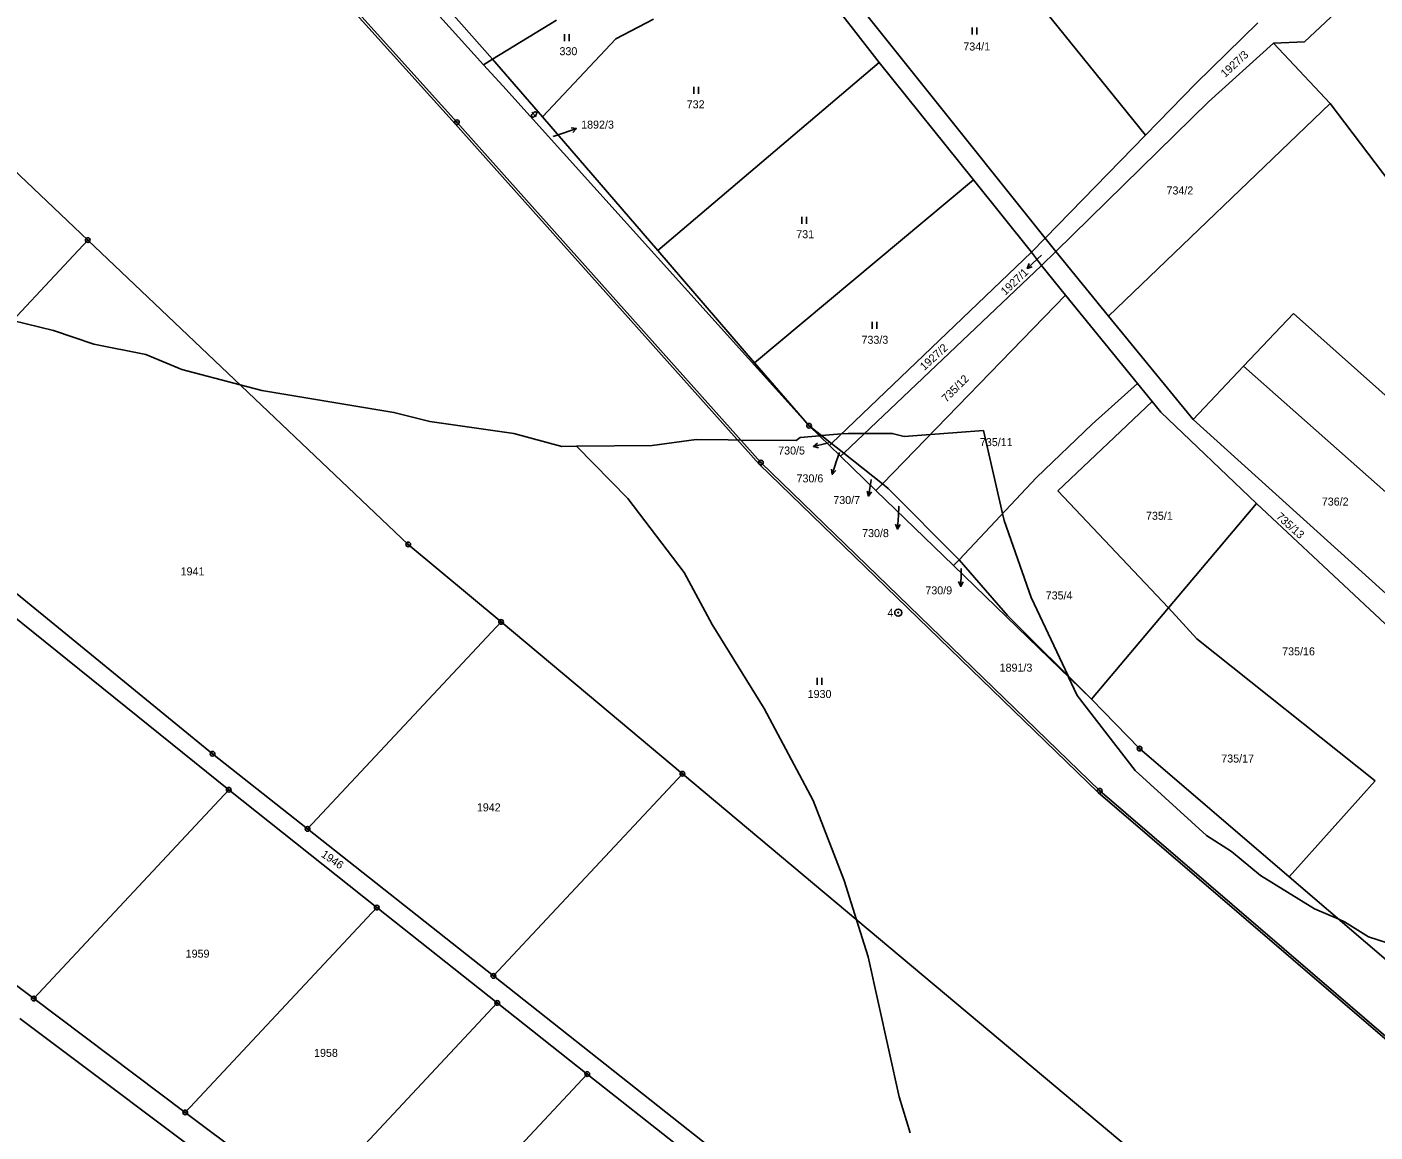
# Model space of a CAD drawing. Extents: x -445050 to -440454, y -1134563 to -1129741.
# Drawn here: x -442192.6 to -441906.2, y -1131669.9 to -1131435.1 of the extents above; entities that cross this region are included whole.
import ezdxf

# ---------------------------------------------------------------- set-up
doc = ezdxf.new("R2010")
doc.units = 0
for name, color, linetype in [('Vrstva 1', 7, 'Continuous'), ('Vrstva 16', 7, 'Continuous'), ('Vrstva 17', 7, 'Continuous'), ('Vrstva 18', 7, 'Continuous'), ('Vrstva 24', 7, 'Continuous'), ('Vrstva 25', 7, 'Continuous'), ('Vrstva 5', 7, 'Continuous'), ('Vrstva 52', 7, 'Continuous'), ('Vrstva 6', 7, 'Continuous')]:
    doc.layers.add(name, color=color, linetype=linetype)

msp = doc.modelspace()

# ---------------------------------------------------------------- linework, layer by layer
at = {"layer": 'Vrstva 1'}
for points in [[(-442157.37, -1131374.74), (-442095.56, -1131443.13)], [(-442168.28, -1131380.99), (-442101.24, -1131455.36)], [(-442179.67, -1131480.38), (-442268.09, -1131396.29)], [(-442113.45, -1131419.55), (-442093.65, -1131441.96)], [(-441902.17, -1131420.45), (-441921.19, -1131438.24)], [(-441944.24, -1131447.15), (-441931.04, -1131434.21)], [(-441927.72, -1131438.57), (-441941.58, -1131451.05)], [(-441921.19, -1131438.24), (-441927.72, -1131438.57)], [(-442095.56, -1131443.13), (-442093.65, -1131441.96)], [(-442093.65, -1131441.96), (-442083.08, -1131454.2)], [(-442095.56, -1131443.13), (-442091.49, -1131447.63)], [(-442091.49, -1131447.63), (-442026.4, -1131519.85)], [(-441954.96, -1131458.13), (-441944.24, -1131447.15)], [(-441941.58, -1131451.05), (-441974, -1131482.84)], [(-442083.08, -1131454.2), (-442058.58, -1131482.58)], [(-442101.24, -1131455.36), (-442036.66, -1131527.66)], [(-441976.29, -1131480), (-441954.96, -1131458.13)], [(-441979.19, -1131482.97), (-441976.29, -1131480)], [(-442226.04, -1131529.98), (-442179.67, -1131480.38)], [(-442179.67, -1131480.38), (-442111.57, -1131545.05)], [(-442058.58, -1131482.58), (-442037.98, -1131506.44)], [(-442021.64, -1131523.62), (-441979.19, -1131482.97)], [(-441974, -1131482.84), (-441977.03, -1131485.81)], [(-441977.03, -1131485.81), (-442019.04, -1131525.68)], [(-442037.98, -1131506.44), (-442026.4, -1131519.85)], [(-442022.08, -1131524.04), (-442026.4, -1131519.85)], [(-442026.4, -1131519.85), (-442021.64, -1131523.62)], [(-442019.72, -1131526.33), (-442022.08, -1131524.04)], [(-442021.64, -1131523.62), (-442019.04, -1131525.68)], [(-442019.04, -1131525.68), (-442010.83, -1131532.18)], [(-442036.66, -1131527.66), (-441964.66, -1131597.4)], [(-442012.21, -1131533.6), (-442019.72, -1131526.33)], [(-442226.04, -1131529.98), (-442153.16, -1131589.53)], [(-441995.73, -1131549.56), (-442012.21, -1131533.6)], [(-442010.83, -1131532.18), (-442009.59, -1131533.16)], [(-442009.59, -1131533.16), (-441994.54, -1131548.3)], [(-441931.33, -1131536.38), (-441950.03, -1131558.53)], [(-441889.88, -1131575.15), (-441931.33, -1131536.38)], [(-442091.86, -1131561.52), (-442111.57, -1131545.05)], [(-441994.54, -1131548.3), (-441984.26, -1131560.14)], [(-441966.42, -1131577.94), (-441995.73, -1131549.56)], [(-442149.7, -1131597.19), (-442196.04, -1131559.85)], [(-441984.26, -1131560.14), (-441966.42, -1131577.94)], [(-441950.03, -1131558.53), (-441966.42, -1131577.94)], [(-442132.97, -1131605.49), (-442091.86, -1131561.52)], [(-442091.86, -1131561.52), (-442073.47, -1131576.89)], [(-442073.47, -1131576.89), (-442053.33, -1131593.78)], [(-441966.42, -1131577.94), (-441956.19, -1131588.42)], [(-442191.15, -1131641.54), (-442265.74, -1131585.81)], [(-441956.19, -1131588.42), (-441924.38, -1131615.68)], [(-442153.16, -1131589.53), (-442132.97, -1131605.49)], [(-442053.33, -1131593.78), (-442093.48, -1131636.72)], [(-442053.33, -1131593.78), (-441953.38, -1131677.57)], [(-442149.7, -1131597.19), (-442191.15, -1131641.54)], [(-442118.26, -1131622.2), (-442149.7, -1131597.19)], [(-441964.66, -1131597.4), (-441891.82, -1131659.94)], [(-442093.48, -1131636.72), (-442132.97, -1131605.49)], [(-441924.38, -1131615.68), (-441883.61, -1131650.62)], [(-442118.26, -1131622.2), (-442158.95, -1131665.72)], [(-442092.66, -1131642.46), (-442118.26, -1131622.2)], [(-441953.77, -1131747.17), (-442093.48, -1131636.72)], [(-442158.95, -1131665.72), (-442191.15, -1131641.54)], [(-442132.78, -1131685.37), (-442092.66, -1131642.46)], [(-442092.66, -1131642.46), (-442073.54, -1131657.58)], [(-442053.64, -1131751.13), (-442194.11, -1131645.78)], [(-442073.54, -1131657.58), (-442113.24, -1131700.05)], [(-442053.78, -1131673.2), (-442073.54, -1131657.58)], [(-442132.78, -1131685.37), (-442158.95, -1131665.72)]]:
    msp.add_lwpolyline(points, dxfattribs=at)
at = {"layer": 'Vrstva 16'}
for p, q in [((-442078.68, -1131457.68), (-442075.84, -1131456.71)), ((-441977.88, -1131484.38), (-441980.08, -1131486.42)), ((-442022.56, -1131523.57), (-442025.48, -1131524.25)), ((-442020.56, -1131527.32), (-442021.5, -1131530.17)), ((-442013.33, -1131531.8), (-442013.77, -1131534.77)), ((-442007.45, -1131538.81), (-442007.65, -1131541.8)), ((-441994.11, -1131550.96), (-441994.2, -1131553.96))]:
    msp.add_line(p, q, dxfattribs=at)
for points in [[(-442076.95, -1131456.56), (-442075.84, -1131456.71), (-442076.63, -1131457.51)], [(-442080.82, -1131458.41), (-442078.68, -1131457.68)], [(-441979.01, -1131486.1), (-441980.08, -1131486.42), (-441979.69, -1131485.37)], [(-441977.06, -1131483.63), (-441977.88, -1131484.38)], [(-442024.39, -1131524.51), (-442025.48, -1131524.25), (-442024.62, -1131523.54)], [(-442022.27, -1131523.5), (-442022.56, -1131523.57)], [(-442019.97, -1131525.55), (-442020.56, -1131527.32)], [(-442020.71, -1131529.38), (-442021.5, -1131530.17), (-442021.66, -1131529.06)], [(-442013.26, -1131531.29), (-442013.33, -1131531.8)], [(-442013.13, -1131533.85), (-442013.77, -1131534.77), (-442014.11, -1131533.71)], [(-442007.32, -1131536.9), (-442007.45, -1131538.81)], [(-442007.09, -1131540.84), (-442007.65, -1131541.8), (-442008.08, -1131540.77)], [(-441994.08, -1131550.16), (-441994.11, -1131550.96)], [(-441993.67, -1131552.97), (-441994.2, -1131553.96), (-441994.67, -1131552.94)]]:
    msp.add_lwpolyline(points, dxfattribs=at)
at = {"layer": 'Vrstva 24'}
for centre, radius in [((-442101.24, -1131455.36), 0.5), ((-442101.24, -1131455.36), 0.1), ((-442179.67, -1131480.38), 0.5), ((-442179.67, -1131480.38), 0.1), ((-442026.4, -1131519.85), 0.5), ((-442026.4, -1131519.85), 0.1), ((-442036.66, -1131527.66), 0.5), ((-442036.66, -1131527.66), 0.1), ((-442111.57, -1131545.05), 0.5), ((-442111.57, -1131545.05), 0.1), ((-442007.48, -1131559.55), 0.75), ((-442007.48, -1131559.55), 0.1), ((-442091.86, -1131561.52), 0.5), ((-442091.86, -1131561.52), 0.1), ((-441956.19, -1131588.42), 0.5), ((-441956.19, -1131588.42), 0.1), ((-442153.16, -1131589.53), 0.5), ((-442153.16, -1131589.53), 0.1), ((-442053.33, -1131593.78), 0.5), ((-442053.33, -1131593.78), 0.1), ((-442149.7, -1131597.19), 0.5), ((-442149.7, -1131597.19), 0.1), ((-441964.66, -1131597.4), 0.5), ((-441964.66, -1131597.4), 0.1), ((-442132.97, -1131605.49), 0.5), ((-442132.97, -1131605.49), 0.1), ((-442118.26, -1131622.2), 0.5), ((-442118.26, -1131622.2), 0.1), ((-442093.48, -1131636.72), 0.5), ((-442093.48, -1131636.72), 0.1), ((-442191.15, -1131641.54), 0.5), ((-442191.15, -1131641.54), 0.1), ((-442092.66, -1131642.46), 0.5), ((-442092.66, -1131642.46), 0.1), ((-442073.54, -1131657.58), 0.5), ((-442073.54, -1131657.58), 0.1), ((-442158.95, -1131665.72), 0.5), ((-442158.95, -1131665.72), 0.1)]:
    msp.add_circle(centre, radius, dxfattribs=at)
at = {"layer": 'Vrstva 25'}
for p, q in [((-442078.4, -1131438.16), (-442078.4, -1131436.66)), ((-442077.4, -1131438.16), (-442077.4, -1131436.66)), ((-441991.79, -1131436.72), (-441991.79, -1131435.22)), ((-441990.79, -1131436.72), (-441990.79, -1131435.22)), ((-442050.92, -1131449.31), (-442050.92, -1131447.81)), ((-442049.92, -1131449.31), (-442049.92, -1131447.81)), ((-442085.31, -1131453.68), (-442084.83, -1131453.21)), ((-442085.3, -1131453.2), (-442084.37, -1131454.17)), ((-442084.36, -1131453.7), (-442084.85, -1131454.16)), ((-442027.97, -1131476.92), (-442027.97, -1131475.42)), ((-442026.97, -1131476.92), (-442026.97, -1131475.42)), ((-442013.01, -1131499.24), (-442013.01, -1131497.74)), ((-442012.01, -1131499.24), (-442012.01, -1131497.74)), ((-442024.72, -1131574.92), (-442024.72, -1131573.42)), ((-442023.72, -1131574.92), (-442023.72, -1131573.42))]:
    msp.add_line(p, q, dxfattribs=at)
for centre, start, end in [((-442085.08, -1131453.92), 133.8308, 313.8308), ((-442084.6, -1131453.45), 313.8308, 133.8308)]:
    msp.add_arc(centre, 0.335, start, end, dxfattribs=at)
at = {"layer": 'Vrstva 5'}
for points in [[(-442169.05, -1131380.87), (-442101.61, -1131455.69)], [(-442101.61, -1131455.69), (-442037.01, -1131528.02)], [(-442037.01, -1131528.02), (-441965.01, -1131597.76)], [(-441965.01, -1131597.76), (-441892.15, -1131660.32)]]:
    msp.add_lwpolyline(points, dxfattribs=at)
at = {"layer": 'Vrstva 52'}
for points in [[(-442195.64, -1131497.46), (-442186.92, -1131499.57), (-442178.41, -1131502.54), (-442167.36, -1131504.67), (-442159.7, -1131507.86), (-442147.32, -1131511.11), (-442142.7, -1131512.32), (-442114.63, -1131517), (-442106.98, -1131518.91), (-442089.12, -1131521.46)], [(-442089.12, -1131521.46), (-442078.92, -1131524.23), (-442075.85, -1131524.21)], [(-442075.85, -1131524.21), (-442059.78, -1131524.01), (-442050.43, -1131522.74), (-442043.63, -1131522.86), (-442040.93, -1131522.88), (-442029.17, -1131522.95), (-442028.32, -1131522.31), (-442024.21, -1131521.97), (-442023.77, -1131521.93), (-442019.51, -1131521.58), (-442018.12, -1131521.46), (-442014.6, -1131521.46), (-442008.76, -1131521.46), (-442006.21, -1131522.1), (-442000.63, -1131521.68), (-441994.94, -1131521.25), (-441989.36, -1131520.83)], [(-441989.36, -1131520.83), (-441985.29, -1131538.47), (-441984.95, -1131539.96), (-441979.21, -1131556.33), (-441971.4, -1131572.97), (-441971.27, -1131573.24), (-441969.43, -1131577.16), (-441957.1, -1131593.11), (-441942.01, -1131606.93), (-441936.69, -1131610.33), (-441930.53, -1131615.43), (-441919.05, -1131622.45), (-441913.87, -1131624.69), (-441912.67, -1131625.21), (-441907.57, -1131628.4), (-441870.57, -1131640.3)], [(-442075.85, -1131524.21), (-442064.89, -1131535.28), (-442052.98, -1131551.01), (-442047.03, -1131562.07), (-442035.97, -1131579.93), (-442025.56, -1131599.49), (-442018.96, -1131616.49), (-442016.35, -1131624.78), (-442013.86, -1131632.65), (-442007.27, -1131662.41), (-442004.93, -1131670.07)]]:
    msp.add_lwpolyline(points, dxfattribs=at)
at = {"layer": 'Vrstva 6'}
for points in [[(-442003.99, -1131397.31), (-441954.96, -1131458.13)], [(-442027.67, -1131415.64), (-441976.29, -1131480)], [(-442024.23, -1131426.29), (-442011.52, -1131442.64)], [(-442080.11, -1131433.67), (-442093.65, -1131441.96)], [(-442067.48, -1131437.61), (-442059.44, -1131433.42)], [(-442067.48, -1131437.61), (-442083.08, -1131454.2)], [(-441927.72, -1131438.57), (-441915.67, -1131451.36)], [(-442011.52, -1131442.64), (-442058.58, -1131482.58)], [(-442011.52, -1131442.64), (-441991.49, -1131467.62)], [(-441915.67, -1131451.36), (-441962.79, -1131496.56)], [(-441915.67, -1131451.36), (-441901.29, -1131470.43)], [(-441991.49, -1131467.62), (-442037.98, -1131506.44)], [(-441991.49, -1131467.62), (-441979.19, -1131482.97)], [(-441976.29, -1131480), (-441974, -1131482.84)], [(-441979.19, -1131482.97), (-441977.03, -1131485.81)], [(-441974, -1131482.84), (-441962.79, -1131496.56)], [(-441977.03, -1131485.81), (-441971.91, -1131492.1)], [(-441971.91, -1131492.1), (-442010.83, -1131532.18)], [(-441971.91, -1131492.1), (-441956.63, -1131510.87)], [(-441962.79, -1131496.56), (-441944.84, -1131518.54)], [(-441934.12, -1131507.2), (-441923.5, -1131495.97)], [(-441923.5, -1131495.97), (-441878.19, -1131536.34)], [(-441944.84, -1131518.54), (-441934.12, -1131507.2)], [(-441934.12, -1131507.2), (-441887.8, -1131548.2)], [(-441966.24, -1131519.5), (-441956.63, -1131510.87)], [(-441956.63, -1131510.87), (-441953.52, -1131514.69)], [(-441953.52, -1131514.69), (-441973.55, -1131533.66)], [(-441953.52, -1131514.69), (-441951.67, -1131516.96)], [(-441951.67, -1131516.96), (-441931.33, -1131536.38)], [(-441978.11, -1131530.84), (-441966.24, -1131519.5)], [(-441944.84, -1131518.54), (-441898, -1131560.79)], [(-442022.08, -1131524.04), (-442021.64, -1131523.62)], [(-442019.04, -1131525.68), (-442019.72, -1131526.33)], [(-441978.11, -1131530.84), (-441994.54, -1131548.3)], [(-442010.83, -1131532.18), (-442012.21, -1131533.6)], [(-441950.03, -1131558.53), (-441973.55, -1131533.66)], [(-441994.54, -1131548.3), (-441995.73, -1131549.56)], [(-441944.03, -1131565.09), (-441950.03, -1131558.53)], [(-441906.13, -1131595.3), (-441944.03, -1131565.09)], [(-441906.13, -1131595.3), (-441924.38, -1131615.68)]]:
    msp.add_lwpolyline(points, dxfattribs=at)

# ---------------------------------------------------------------- texts
at = {"layer": 'Vrstva 16'}
for s, p in [('1892/3', (-442074.84, -1131456.71)), ('730/5', (-442032.98, -1131525.95)), ('730/6', (-442029.08, -1131531.87)), ('730/7', (-442021.27, -1131536.47)), ('730/8', (-442015.15, -1131543.5)), ('730/9', (-442001.71, -1131555.66)), ('1891/3', (-441985.93, -1131572.08))]:
    msp.add_text(s, height=1.7, dxfattribs=at).set_placement(p)
for s, rotation, p in [('1927/1', 43.5865, (-441984.71, -1131492.22)), ('1946', 325.5754, (-442130.23, -1131611.28))]:
    msp.add_text(s, height=1.7, rotation=rotation, dxfattribs=at).set_placement(p)
at = {"layer": 'Vrstva 17'}
msp.add_text('4', height=1.7, dxfattribs=at).set_placement((-442009.75, -1131560.4))
at = {"layer": 'Vrstva 18'}
for s, height, p in [('330', 1.7, (-442079.45, -1131441.11)), ('734/1', 1.7, (-441993.64, -1131440.11)), ('732', 1.7, (-442052.41, -1131452.4)), ('1892/3', 0.1, (-442081.03, -1131458.41)), ('734/2', 1.7, (-441950.48, -1131470.7)), ('731', 1.7, (-442029.14, -1131479.99)), ('1927/1', 0.1, (-441977.26, -1131483.63)), ('733/3', 1.7, (-442015.28, -1131502.42)), ('735/11', 1.7, (-441990.12, -1131524.16)), ('730/5', 0.1, (-442022.46, -1131523.5)), ('730/6', 0.1, (-442020.16, -1131525.55)), ('730/7', 0.1, (-442013.45, -1131531.29)), ('730/8', 0.1, (-442007.51, -1131536.9)), ('736/2', 1.7, (-441917.48, -1131536.8)), ('735/1', 1.7, (-441954.83, -1131539.82)), ('1941', 1.7, (-442159.94, -1131551.63)), ('730/9', 0.1, (-441994.27, -1131550.16)), ('735/4', 1.7, (-441976.14, -1131556.74)), ('735/16', 1.7, (-441925.9, -1131568.62)), ('1930', 1.7, (-442026.72, -1131577.68)), ('735/17', 1.7, (-441938.84, -1131591.39)), ('1942', 1.7, (-442097, -1131601.77)), ('1959', 1.7, (-442158.87, -1131632.85)), ('1958', 1.7, (-442131.59, -1131653.93))]:
    msp.add_text(s, height=height, dxfattribs=at).set_placement(p)
for s, rotation, p in [('1927/3', 42.7914, (-441938.01, -1131445.94)), ('1927/2', 42.5106, (-442001.91, -1131508.2)), ('735/12', 45, (-441997.25, -1131514.96)), ('735/13', 318.2445, (-441927.33, -1131539.35))]:
    msp.add_text(s, height=1.7, rotation=rotation, dxfattribs=at).set_placement(p)

doc.saveas('drawing.dxf')
